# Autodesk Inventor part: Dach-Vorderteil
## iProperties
Created: 2006-12
Part Number: Dach-Vorderteil
Document SubType Name: Modeling
Designer: Mathemaster
Author: Mathemaster
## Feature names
1. Erhebung1
2. Wandstärke2
3. Extrusion1
4. Extrusion2
5. Extrusion3
6. Rundung1 [Fillet]
